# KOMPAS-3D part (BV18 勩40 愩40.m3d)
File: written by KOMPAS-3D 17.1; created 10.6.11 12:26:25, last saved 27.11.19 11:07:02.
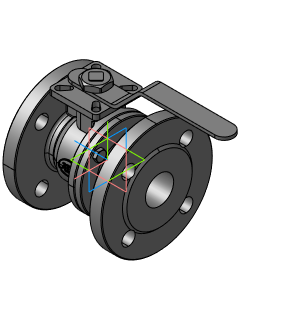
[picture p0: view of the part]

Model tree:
1. Плоскость XY
2. Плоскость ZX
3. Плоскость ZY
4. Ось X
5. Ось Y
6. Ось Z
7. Начало координат
8. Операция без истории:3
